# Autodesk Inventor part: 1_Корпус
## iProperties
Created: 2009-12
Part Number: 1_Корпус
Document SubType Name: Modeling
Designer: Jeck
Density: 1 g/cm^3
Mass: 431.532 g
Surface Area: 700.125 cm^2
Volume: 431.532 cm^3
Author: Jeck
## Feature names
1. Выдавливание1 [Extrusion]
2. Выдавливание2 [Extrusion]
3. Отверстие1 [Hole]
4. Отверстие2 [Hole]
5. Сопряжение1 [Fillet]
6. Отверстие4 [Hole]
7. Отверстие3 [Hole]
8. Зеркальное отражение2 [Mirror]
